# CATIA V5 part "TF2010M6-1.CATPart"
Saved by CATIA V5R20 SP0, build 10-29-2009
Part number: TF2010M6-1
Revision: ANY
Definition: UNKNOWN
Nomenclature: TF2010M6-1
Source: Unknown
Bounding box of the stored display mesh (mm): x -4.95 to 4.95, y 0 to 24.45, z -4.95 to 4.95
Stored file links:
  C:\Users\Utente\Desktop\IO LAVORO\3D X SITO CF\CUMSA\3D files RCM\RCM 204810\TF2010M6-1.CATPart
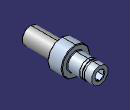
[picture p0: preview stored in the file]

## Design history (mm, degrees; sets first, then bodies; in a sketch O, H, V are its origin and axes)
Body1 "Chaflán2" (main body)
  Solid1: solid without history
